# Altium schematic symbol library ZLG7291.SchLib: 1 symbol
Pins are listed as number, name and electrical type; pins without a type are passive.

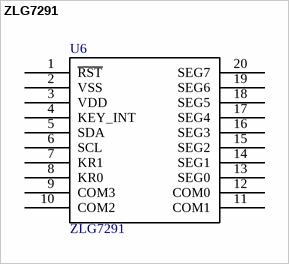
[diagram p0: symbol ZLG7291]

## ZLG7291
designator U6
footprint TSOP65P640X120-20N (TSOP, 20-Leads, Body 6.50x4.40mm, Pitch 0.65mm, IPC Medium Density,ZLGLIB)
pins: 1 ~{RST}, 2 VSS, 3 VDD, 4 KEY_INT, 5 SDA, 6 SCL, 7 KR1, 8 KR0, 9 COM3, 10 COM2, 11 COM1, 12 COM0, 13 SEG0, 14 SEG1, 15 SEG2, 16 SEG3, 17 SEG4, 18 SEG5, 19 SEG6, 20 SEG7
